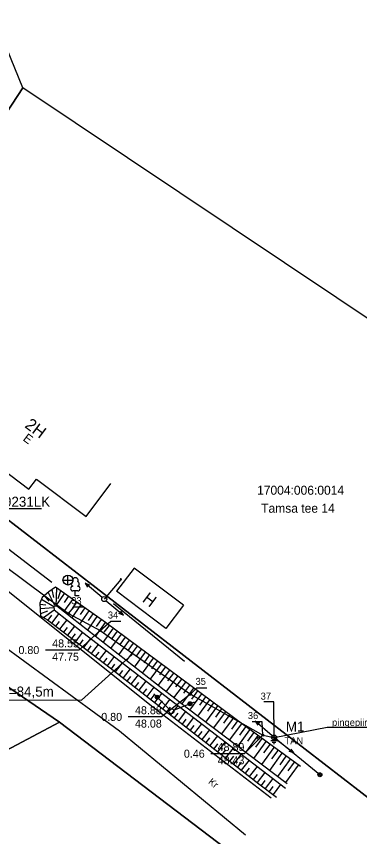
# Model space of a CAD drawing. Extents: x 643977 to 644381, y 6457457 to 6457867.
# Drawn here: x 644254.5 to 644288.8, y 6457546.1 to 6457628.1 of the extents above; entities that cross this region are included whole.
import ezdxf

# ---------------------------------------------------------------- set-up
doc = ezdxf.new("R2010")
doc.units = 0
for name, color, linetype in [('005 MPO EE @ 1 (1)', 7, 'Continuous'), ('005 MPO EE @ 1 (2)', 7, 'Continuous'), ('007 PIIR EE', 7, 'Continuous'), ('007 PIIR1 EE', 7, 'Continuous'), ('010 TXT EE', 7, 'Continuous'), ('MOOTMPUNKT', 7, 'Continuous'), ('TEE', 7, 'Continuous'), ('TORU_NR', 7, 'Continuous'), ('TRUUP', 7, 'Continuous'), ('UUS', 7, 'Continuous'), ('Veeprojekti jooned$0$0_Hoiatustekst', 7, 'Continuous'), ('VORMISTUS', 7, 'Continuous')]:
    doc.layers.add(name, color=color, linetype=linetype)

# ---------------------------------------------------------------- blocks, each defined once
blk = doc.blocks.new('MPSUUN')
at = {"layer": '007 PIIR EE'}
for p, q in [((0, 0), (0, 0)), ((0.5, 0), (5, 0)), ((5, 0), (4.1, 0.3)), ((5, 0), (4.1, -0.3))]:
    blk.add_line(p, q, dxfattribs=at)

msp = doc.modelspace()

# ---------------------------------------------------------------- linework, layer by layer
at = {"layer": '005 MPO EE @ 1 (1)'}
for p, q in [((644264.943, 6457571.802), (644263.286, 6457569.836)), ((644284.852, 6457552.266), (644280.27, 6457555.988))]:
    msp.add_line(p, q, dxfattribs=at)
for points in [[(644248.226, 6457577.956), (644251.586, 6457578.9), (644257.011, 6457578.9)], [(644280.27, 6457555.988), (644285.583, 6457557.035), (644295.236, 6457557.035)]]:
    msp.add_lwpolyline(points, dxfattribs=at)
for centre, radius in [((644263.286, 6457569.836), 0.25), ((644270.008, 6457558.622), 0.25), ((644280.27, 6457555.988), 0.25), ((644284.852, 6457552.266), 0.2)]:
    msp.add_circle(centre, radius, dxfattribs=at)
for start, end in [(0, 180), (180, 0)]:
    msp.add_arc((644264.943, 6457571.802), 0.0625, start, end, dxfattribs=at)
at = {"layer": '005 MPO EE @ 1 (2)'}
for points in [[(644165.209, 6457630.911), (644174.337, 6457623.878), (644186.272, 6457614.624), (644201.035, 6457604.979), (644215.289, 6457597.386), (644225.394, 6457591.42), (644240.377, 6457581.381), (644253.475, 6457570.785), (644267.864, 6457559.308)], [(644223.424, 6457587.828), (644237.787, 6457577.75), (644250.576, 6457567.066), (644264.806, 6457556.67)], [(644267.864, 6457559.308), (644279.984, 6457549.963)], [(644264.806, 6457556.67), (644277.411, 6457546.273)]]:
    msp.add_lwpolyline(points, dxfattribs=at)
at = {"layer": '007 PIIR EE'}
for p, q in [((644261.369, 6457571.441), (644261.619, 6457571.037)), ((644261.369, 6457571.441), (644261.811, 6457571.265)), ((644263.095, 6457569.997), (644261.369, 6457571.441)), ((644263.478, 6457569.676), (644265.203, 6457568.232)), ((644265.203, 6457568.232), (644264.762, 6457568.408)), ((644265.203, 6457568.232), (644264.954, 6457568.636))]:
    msp.add_line(p, q, dxfattribs=at)
at = {"layer": '007 PIIR1 EE'}
for points in [[(644212.727, 6457604.721), (644212.787, 6457603.384), (644212.635, 6457602.989), (644212.886, 6457602.359), (644220.606, 6457597.153), (644222.47, 6457596.063), (644231.114, 6457590.695), (644237.777, 6457585.353), (644242.629, 6457581.344), (644246.678, 6457578.098), (644259.713, 6457568.388), (644262.891, 6457566.699), (644271.921, 6457560.313), (644279.137, 6457556.219), (644280.27, 6457555.988)], [(644212.727, 6457604.721), (644212.787, 6457603.384), (644212.635, 6457602.989), (644212.886, 6457602.359), (644220.606, 6457597.153), (644222.47, 6457596.063), (644231.114, 6457590.695), (644237.777, 6457585.353), (644242.629, 6457581.344), (644246.678, 6457578.098), (644259.713, 6457568.388), (644262.891, 6457566.699), (644271.921, 6457560.313), (644279.137, 6457556.219), (644280.27, 6457555.988)], [(644262.891, 6457566.699), (644260.75, 6457564.736), (644257.417, 6457564.736)], [(644230.795, 6457559.763), (644261.004, 6457559.737), (644266.084, 6457564.289)], [(644271.921, 6457560.313), (644269.031, 6457558.054), (644265.697, 6457558.054)], [(644279.137, 6457556.219), (644277.292, 6457554.374), (644273.959, 6457554.374)], [(644280.27, 6457555.988), (644280.27, 6457555.649)], [(644280.588, 6457555.649), (644279.952, 6457555.649)], [(644280.454, 6457555.499), (644280.086, 6457555.499)], [(644280.32, 6457555.349), (644280.22, 6457555.349)]]:
    msp.add_lwpolyline(points, dxfattribs=at)
at = {"layer": '010 TXT EE'}
for p, q in [((644259.663, 6457571.241), (644259.663, 6457572.241)), ((644259.163, 6457571.741), (644260.163, 6457571.741))]:
    msp.add_line(p, q, dxfattribs=at)
msp.add_circle((644259.663, 6457571.741), 0.5, dxfattribs=at)
at = {"layer": 'Defpoints'}
for points in [[(644248.488, 6457593.021), (644245.977, 6457589.68), (644250.898, 6457585.981), (644250.174, 6457585.019), (644255.762, 6457580.818), (644256.522, 6457581.827), (644261.477, 6457578.102), (644263.952, 6457581.395)], [(644271.202, 6457569.232), (644266.269, 6457572.937), (644264.525, 6457570.615)], [(644271.202, 6457569.232), (644269.457, 6457566.909), (644264.525, 6457570.615)]]:
    msp.add_lwpolyline(points, dxfattribs=at)
at = {"layer": 'MOOTMPUNKT'}
for centre in [(644259.713, 6457568.388), (644262.891, 6457566.699), (644271.921, 6457560.313), (644278.694, 6457555.911), (644279.137, 6457556.219), (644280.27, 6457555.988), (644284.852, 6457552.266)]:
    msp.add_circle(centre, 0.1, dxfattribs=at)
at = {"layer": 'TEE'}
msp.add_lwpolyline([(644119.21, 6457655.5), (644137.18, 6457639.57), (644176.94, 6457610.8), (644193.44, 6457599.42), (644220.94, 6457583.42), (644258.83, 6457557.54), (644299.64, 6457526.51), (644330.13, 6457505.12), (644351.66, 6457500.83), (644373.13, 6457501.25), (644368.81, 6457508.24), (644366.6, 6457513.63), (644352.78, 6457513.35), (644335.16, 6457516.88), (644304.29, 6457538.7), (644233.94, 6457592.97), (644213.34, 6457605.08), (644212.32, 6457605.7), (644192.23, 6457620.22), (644172.44, 6457634.51), (644128.57, 6457664.58), (644105.62, 6457695.4)], dxfattribs=at)
for points in [[(644249.59, 6457612.49), (644255.15, 6457620.97), (644245.1, 6457645.66), (644228.29, 6457625.32), (644212.32, 6457605.7), (644213.34, 6457605.08), (644233.94, 6457592.97)], [(644233.94, 6457592.97), (644304.29, 6457538.7), (644328.42, 6457571.95), (644255.15, 6457620.97), (644249.59, 6457612.49)], [(644187.08, 6457554.88), (644204.95, 6457528.94), (644258.83, 6457557.54), (644220.94, 6457583.42), (644193.44, 6457599.42), (644191.21, 6457575.04)], [(644258.83, 6457557.54), (644204.95, 6457528.94), (644209.32, 6457456.67), (644282.85, 6457490.46), (644299.64, 6457526.51)]]:
    msp.add_lwpolyline(points, close=True, dxfattribs=at)
at = {"layer": 'TORU_NR'}
for p, q in [((644258.034, 6457571.483), (644247.502, 6457579.582)), ((644271.307, 6457563.578), (644264.214, 6457569.353))]:
    msp.add_line(p, q, dxfattribs=at)
at = {"layer": 'TRUUP'}
for p, q in [((644258.239, 6457570.008), (644258.097, 6457570.804)), ((644258.509, 6457570.964), (644258.437, 6457569.121)), ((644258.914, 6457570.672), (644258.653, 6457569.875)), ((644257.005, 6457569.81), (644258.26, 6457569.109)), ((644257.786, 6457569.64), (644257.311, 6457570.189)), ((644258.352, 6457569.184), (644257.689, 6457570.516)), ((644258.437, 6457569.121), (644259.32, 6457570.379)), ((644259.265, 6457568.56), (644260.139, 6457569.805)), ((644259.3, 6457569.48), (644259.73, 6457570.092)), ((644256.848, 6457569.342), (644257.44, 6457569.248)), ((644258.265, 6457568.944), (644256.884, 6457568.844)), ((644260.053, 6457567.942), (644260.957, 6457569.23)), ((644260.103, 6457568.884), (644260.548, 6457569.518)), ((644260.907, 6457568.288), (644261.367, 6457568.943)), ((644257.632, 6457568.632), (644256.92, 6457568.345)), ((644257.211, 6457568), (644258.269, 6457568.766)), ((644258, 6457568.211), (644257.634, 6457567.733)), ((644258.759, 6457568.378), (644258.03, 6457567.428)), ((644260.841, 6457567.325), (644261.776, 6457568.656)), ((644261.63, 6457566.707), (644262.594, 6457568.081)), ((644261.71, 6457567.692), (644262.185, 6457568.369)), ((644258.789, 6457567.596), (644258.427, 6457567.124)), ((644259.543, 6457567.758), (644258.824, 6457566.82)), ((644262.418, 6457566.09), (644263.413, 6457567.507)), ((644262.514, 6457567.096), (644263.004, 6457567.794)), ((644259.578, 6457566.981), (644259.221, 6457566.516)), ((644260.327, 6457567.137), (644259.617, 6457566.211)), ((644261.112, 6457566.516), (644260.411, 6457565.603)), ((644263.168, 6457565.502), (644264.215, 6457566.91)), ((644263.294, 6457566.51), (644263.814, 6457567.209)), ((644264.089, 6457565.903), (644264.617, 6457566.612)), ((644260.367, 6457566.367), (644260.014, 6457565.907)), ((644261.158, 6457565.755), (644260.808, 6457565.298)), ((644261.904, 6457565.907), (644261.204, 6457564.994)), ((644263.955, 6457564.886), (644265.018, 6457566.314)), ((644264.743, 6457564.269), (644265.82, 6457565.717)), ((644264.884, 6457565.296), (644265.419, 6457566.015)), ((644261.951, 6457565.146), (644261.601, 6457564.69)), ((644262.697, 6457565.298), (644261.998, 6457564.386)), ((644265.53, 6457563.652), (644266.622, 6457565.12)), ((644265.679, 6457564.689), (644266.221, 6457565.418)), ((644266.474, 6457564.082), (644267.024, 6457564.821)), ((644262.744, 6457564.537), (644262.395, 6457564.081)), ((644263.49, 6457564.688), (644262.791, 6457563.777)), ((644264.283, 6457564.079), (644263.585, 6457563.168)), ((644266.318, 6457563.035), (644267.425, 6457564.523)), ((644267.269, 6457563.476), (644267.826, 6457564.225)), ((644263.538, 6457563.928), (644263.188, 6457563.473)), ((644264.331, 6457563.319), (644263.982, 6457562.864)), ((644265.084, 6457563.465), (644264.378, 6457562.559)), ((644267.105, 6457562.418), (644268.227, 6457563.926)), ((644267.893, 6457561.802), (644269.029, 6457563.329)), ((644268.064, 6457562.869), (644268.628, 6457563.628)), ((644265.126, 6457562.706), (644264.772, 6457562.252)), ((644265.877, 6457562.855), (644265.167, 6457561.944)), ((644268.68, 6457561.185), (644269.832, 6457562.732)), ((644268.859, 6457562.262), (644269.431, 6457563.031)), ((644269.654, 6457561.655), (644270.233, 6457562.434)), ((644265.917, 6457562.094), (644265.561, 6457561.637)), ((644266.67, 6457562.246), (644265.955, 6457561.33)), ((644267.463, 6457561.637), (644266.744, 6457560.715)), ((644269.468, 6457560.568), (644270.634, 6457562.135)), ((644270.255, 6457559.951), (644271.436, 6457561.539)), ((644270.448, 6457561.048), (644271.035, 6457561.837)), ((644266.708, 6457561.482), (644266.35, 6457561.022)), ((644267.499, 6457560.87), (644267.138, 6457560.407)), ((644268.256, 6457561.028), (644267.532, 6457560.1)), ((644271.043, 6457559.334), (644272.239, 6457560.942)), ((644271.243, 6457560.441), (644271.838, 6457561.24)), ((644268.29, 6457560.258), (644267.927, 6457559.792)), ((644269.049, 6457560.419), (644268.321, 6457559.485)), ((644271.834, 6457558.722), (644273.041, 6457560.345)), ((644272.038, 6457559.835), (644272.64, 6457560.643)), ((644272.838, 6457559.234), (644273.442, 6457560.046)), ((644269.081, 6457559.646), (644268.715, 6457559.177)), ((644269.842, 6457559.81), (644269.11, 6457558.87)), ((644270.636, 6457559.201), (644269.898, 6457558.255)), ((644272.633, 6457558.12), (644273.843, 6457559.748)), ((644273.431, 6457557.518), (644274.646, 6457559.151)), ((644273.638, 6457558.634), (644274.245, 6457559.45)), ((644269.871, 6457559.034), (644269.504, 6457558.562)), ((644270.662, 6457558.422), (644270.293, 6457557.948)), ((644271.429, 6457558.592), (644270.687, 6457557.64)), ((644274.229, 6457556.916), (644275.448, 6457558.554)), ((644274.439, 6457558.035), (644275.047, 6457558.853)), ((644275.239, 6457557.435), (644275.849, 6457558.256)), ((644271.453, 6457557.81), (644271.081, 6457557.333)), ((644272.222, 6457557.982), (644271.475, 6457557.025)), ((644275.028, 6457556.314), (644276.25, 6457557.957)), ((644276.039, 6457556.836), (644276.652, 6457557.659)), ((644272.244, 6457557.198), (644271.87, 6457556.718)), ((644273.015, 6457557.373), (644272.264, 6457556.41)), ((644273.035, 6457556.586), (644272.658, 6457556.103)), ((644273.808, 6457556.764), (644273.053, 6457555.795)), ((644275.826, 6457555.712), (644277.053, 6457557.36)), ((644276.64, 6457555.098), (644277.859, 6457556.769)), ((644276.848, 6457556.232), (644277.455, 6457557.064)), ((644273.826, 6457555.974), (644273.447, 6457555.488)), ((644274.601, 6457556.155), (644273.841, 6457555.181)), ((644277.438, 6457554.496), (644278.667, 6457556.179)), ((644277.651, 6457555.636), (644278.263, 6457556.474)), ((644278.454, 6457555.04), (644279.071, 6457555.885)), ((644274.617, 6457555.362), (644274.236, 6457554.873)), ((644275.394, 6457555.546), (644274.63, 6457554.566)), ((644278.237, 6457553.894), (644279.475, 6457555.59)), ((644279.035, 6457553.292), (644280.282, 6457555)), ((644279.257, 6457554.444), (644279.878, 6457555.295)), ((644275.407, 6457554.75), (644275.024, 6457554.258)), ((644276.187, 6457554.937), (644275.418, 6457553.951)), ((644276.198, 6457554.138), (644275.813, 6457553.643)), ((644276.98, 6457554.328), (644276.207, 6457553.336)), ((644279.834, 6457552.69), (644281.09, 6457554.411)), ((644280.06, 6457553.848), (644280.686, 6457554.705)), ((644276.989, 6457553.526), (644276.601, 6457553.028)), ((644277.773, 6457553.718), (644276.996, 6457552.721)), ((644280.632, 6457552.087), (644281.898, 6457553.821)), ((644280.863, 6457553.252), (644281.494, 6457554.116)), ((644281.666, 6457552.656), (644282.302, 6457553.526)), ((644277.78, 6457552.914), (644277.39, 6457552.414)), ((644278.567, 6457553.109), (644277.784, 6457552.106)), ((644279.36, 6457552.5), (644278.573, 6457551.491)), ((644281.431, 6457551.485), (644282.705, 6457553.231)), ((644278.571, 6457552.302), (644278.179, 6457551.799)), ((644279.353, 6457551.7), (644278.971, 6457551.188)), ((644280.132, 6457551.907), (644279.371, 6457550.889)), ((644280.15, 6457551.096), (644279.772, 6457550.59)), ((644280.925, 6457551.298), (644280.173, 6457550.291))]:
    msp.add_line(p, q, dxfattribs=at)
for points in [[(644282.907, 6457553.084), (644277.248, 6457557.215), (644263.426, 6457567.498), (644259.319, 6457570.38), (644258.422, 6457571.026), (644257.74, 6457570.56), (644257.076, 6457569.986), (644256.843, 6457569.412), (644256.932, 6457568.174), (644257.619, 6457567.744), (644264.313, 6457562.61), (644278.742, 6457551.359), (644280.522, 6457550.03)], [(644281.592, 6457551.363), (644271.568, 6457558.923), (644258.538, 6457569.129), (644258.26, 6457569.109), (644258.269, 6457568.766), (644261.145, 6457566.49), (644281.418, 6457550.919)]]:
    msp.add_lwpolyline(points, dxfattribs=at)
at = {"layer": 'UUS'}
for points in [[(644259.713, 6457568.388), (644260.298, 6457569.064), (644261.298, 6457569.064)], [(644262.891, 6457566.699), (644263.943, 6457567.628), (644264.943, 6457567.628)], [(644271.921, 6457560.313), (644272.55, 6457560.965), (644273.55, 6457560.965)], [(644280.27, 6457555.988), (644280.259, 6457559.564), (644279.259, 6457559.564)], [(644279.137, 6457556.219), (644279.075, 6457557.567), (644278.075, 6457557.567)]]:
    msp.add_lwpolyline(points, dxfattribs=at)
at = {"layer": 'Veeprojekti jooned$0$0_Hoiatustekst'}
for p, q in [((644269.83, 6457558.798), (644268.235, 6457560.372)), ((644270.239, 6457558.715), (644272.319, 6457559.55))]:
    msp.add_line(p, q, dxfattribs=at)
for centre, radius in [((644268.588, 6457560.023), 0.199), ((644268.588, 6457560.023), 0.19), ((644268.588, 6457560.023), 0.18), ((644268.588, 6457560.023), 0.171), ((644268.588, 6457560.023), 0.162), ((644268.588, 6457560.023), 0.152), ((644268.588, 6457560.023), 0.143), ((644268.588, 6457560.023), 0.133), ((644268.588, 6457560.023), 0.124), ((644268.588, 6457560.023), 0.114), ((644268.588, 6457560.023), 0.105), ((644268.588, 6457560.023), 0.0953), ((644268.588, 6457560.023), 0.0858), ((644268.588, 6457560.023), 0.0763), ((644268.588, 6457560.023), 0.0669), ((644268.588, 6457560.023), 0.0574), ((644268.588, 6457560.023), 0.0479), ((644268.588, 6457560.023), 0.0385), ((644268.588, 6457560.023), 0.029), ((644268.588, 6457560.023), 0.0195), ((644268.588, 6457560.023), 0.0101), ((644268.588, 6457560.023), 0.00061), ((644271.858, 6457559.365), 0.199), ((644271.858, 6457559.365), 0.19), ((644271.858, 6457559.365), 0.18), ((644271.858, 6457559.365), 0.171), ((644271.858, 6457559.365), 0.162), ((644271.858, 6457559.365), 0.152), ((644271.858, 6457559.365), 0.143), ((644271.858, 6457559.365), 0.133), ((644271.858, 6457559.365), 0.124), ((644271.858, 6457559.365), 0.114), ((644271.858, 6457559.365), 0.105), ((644271.858, 6457559.365), 0.0953), ((644271.858, 6457559.365), 0.0858), ((644271.858, 6457559.365), 0.0763), ((644271.858, 6457559.365), 0.0669), ((644271.858, 6457559.365), 0.0574), ((644271.858, 6457559.365), 0.0479), ((644271.858, 6457559.365), 0.0385), ((644271.858, 6457559.365), 0.029), ((644271.858, 6457559.365), 0.0195), ((644271.858, 6457559.365), 0.0101), ((644271.858, 6457559.365), 0.00061)]:
    msp.add_circle(centre, radius, dxfattribs=at)
at = {"layer": 'VORMISTUS'}
for p, q in [((644260.635, 6457570.644), (644260.155, 6457570.644)), ((644260.395, 6457570.169), (644260.395, 6457570.644)), ((644260.775, 6457570.169), (644260.395, 6457570.169))]:
    msp.add_line(p, q, dxfattribs=at)
for centre, radius, start, end in [((644260.225, 6457571.341), 0.233, 109.02174, 253.14154), ((644260.395, 6457571.689), 0.277, 332.5799, 207.4201), ((644260.565, 6457571.341), 0.233, 286.85082, 70.98591), ((644260.157, 6457570.881), 0.238, 90.0016, 269.3953), ((644260.632, 6457570.881), 0.238, 270.6047, 89.9984)]:
    msp.add_arc(centre, radius, start, end, dxfattribs=at)

# ---------------------------------------------------------------- block references
at = {"layer": '007 PIIR EE'}
for xscale, yscale, rotation in [(0.5000000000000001, 0.4999999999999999, 138.73255725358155), (0.5, 0.5, -38.16408343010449)]:
    msp.add_blockref('MPSUUN', (644280.27, 6457555.988), dxfattribs=dict(at, xscale=xscale, yscale=yscale, rotation=rotation))

# ---------------------------------------------------------------- texts
at = {"layer": '005 MPO EE @ 1 (1)'}
for s, height, p in [('119231LK', 1, (644251.781, 6457579.069)), ('M1', 1, (644281.448, 6457556.586)), ('pingepiirikud LVA440', 0.7, (644286.065, 6457557.15)), ('TAN', 0.7, (644281.315, 6457555.319))]:
    msp.add_text(s, height=height, dxfattribs=at).set_placement(p)
at = {"layer": '005 MPO EE @ 1 (2)'}
msp.add_text('Kr', height=0.7, rotation=320.00064, dxfattribs=at).set_placement((644273.631, 6457551.464))
at = {"layer": '007 PIIR1 EE'}
for s, height, p in [('48.55', 0.8, (644258.084, 6457565.003)), ('0.80', 0.8, (644254.711, 6457564.336)), ('47.75', 0.8, (644258.084, 6457563.669)), ('Nr 11103 40782JK-M1 AXPK4x120 L=84,5m', 1, (644231.595, 6457560.086)), ('48.88', 0.8, (644266.364, 6457558.321)), ('0.80', 0.8, (644262.991, 6457557.654)), ('48.08', 0.8, (644266.364, 6457556.987)), ('48.89', 0.8, (644274.626, 6457554.641)), ('0.46', 0.8, (644271.253, 6457553.974)), ('48.43', 0.8, (644274.626, 6457553.308))]:
    msp.add_text(s, height=height, dxfattribs=at).set_placement(p)
at = {"layer": 'Defpoints'}
for s, height, rotation, p in [('2H', 1.2, 323.0655, (644255.26, 6457587.062)), ('E', 0.9, 323.0655, (644255.089, 6457585.748)), ('H', 1.2, 323.08583, (644267.007, 6457569.644))]:
    msp.add_text(s, height=height, rotation=rotation, dxfattribs=at).set_placement(p)
at = {"layer": 'TEE'}
for s, p in [('17004:006:0014', (644278.571, 6457580.269)), ('Tamsa tee 14', (644278.98, 6457578.469))]:
    msp.add_text(s, height=0.9, dxfattribs=at).set_placement(p)
at = {"layer": 'UUS'}
for s, p in [(' 33', (644259.726, 6457569.326)), (' 34', (644263.391, 6457567.891)), (' 35', (644272.155, 6457561.257)), (' 37', (644278.667, 6457559.777)), (' 36', (644277.385, 6457557.839))]:
    msp.add_text(s, height=0.7, dxfattribs=at).set_placement(p)

doc.saveas('drawing.dxf')
